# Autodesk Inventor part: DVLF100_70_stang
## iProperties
Created: 2010-03
Part Number: DVLF100_70_stang
Document SubType Name: Modeling
Designer: TB
Mass: 1137.19 g
Surface Area: 747.925 cm^2
Volume: 1137.19 cm^3
Density: 1 g/cm^3
Author: TB
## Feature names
1. Revolution1
2. Fillet1
3. Revolution2
